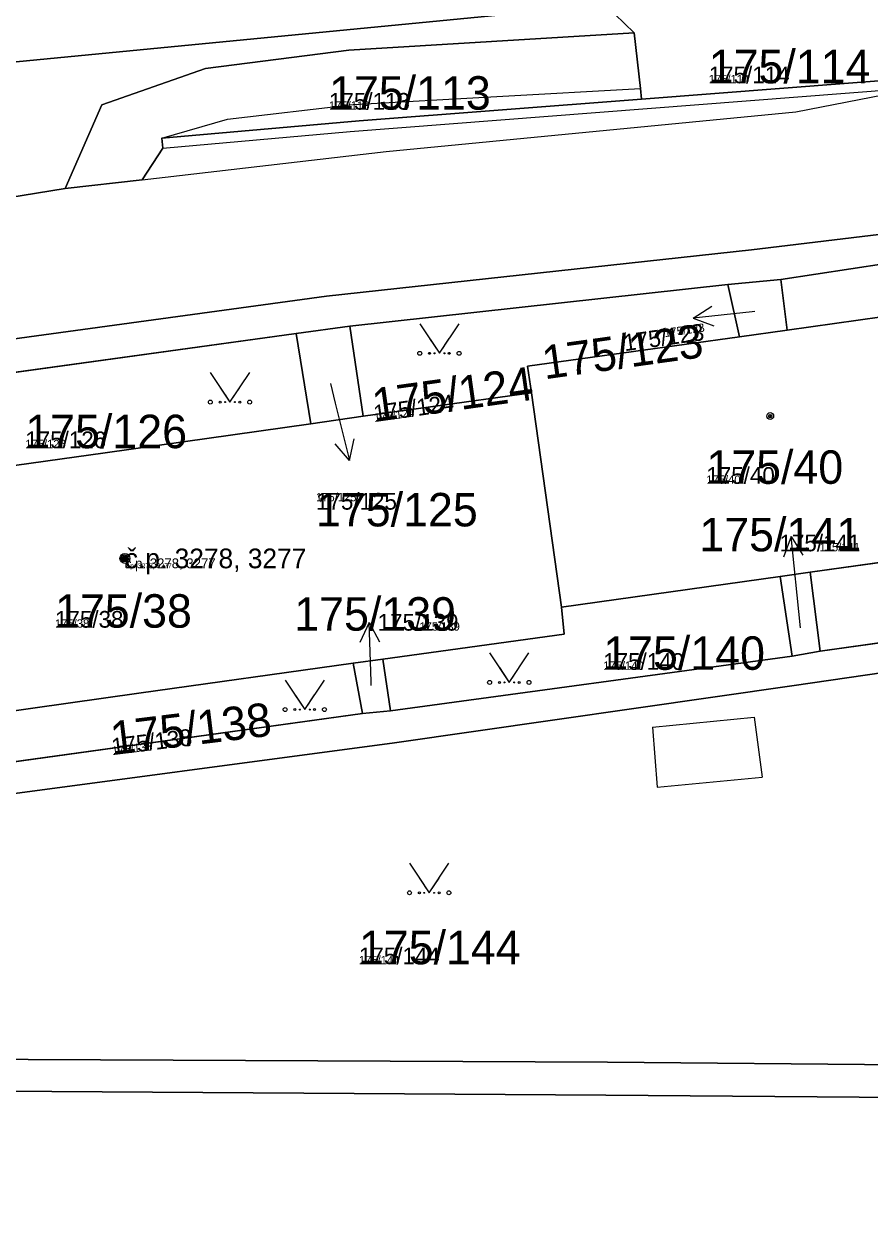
# Model space of a CAD drawing. Extents: x -759873 to -758487, y -975024 to -973516.
# Drawn here: x -759382.7 to -759339.7, y -974652.2 to -974591.1 of the extents above; entities that cross this region are included whole.
import ezdxf

# ---------------------------------------------------------------- set-up
doc = ezdxf.new("R2010")
doc.units = 0
for name, color, linetype in [('KAT_02_hranice parcel', 7, 'Continuous'), ('KAT_03_1000_st čísla parcelní', 7, 'Continuous'), ('KAT_03_1000_čísla parcelní', 7, 'Continuous'), ('KAT_03_1000_čísla popisná', 7, 'Continuous'), ('KAT_03_250_st čísla parcelní', 7, 'Continuous'), ('KAT_03_250_čísla parcelní', 7, 'Continuous'), ('KAT_03_250_čísla popisná', 7, 'Continuous'), ('KAT_03_500_st čísla parcelní', 7, 'Continuous'), ('KAT_03_500_čísla parcelní', 7, 'Continuous'), ('KAT_03_500_čísla popisná', 7, 'Continuous'), ('KAT_04_vnitřní kresba', 7, 'Continuous'), ('KAT_05_1000_značky kultur', 7, 'Continuous'), ('KAT_05_250_značky kultur', 7, 'Continuous'), ('KAT_05_500_značky kultur', 7, 'Continuous'), ('KAT_07_1000_značky budov', 7, 'Continuous'), ('KAT_07_250_značky budov', 7, 'Continuous'), ('KAT_07_500_značky budov', 7, 'Continuous'), ('KAT_12_pomocná šipka', 7, 'Continuous'), ('KAT_14_plocha_budovy', 7, 'Continuous'), ('KAT_14_plocha_pozemek', 7, 'Continuous')]:
    doc.layers.add(name, color=color, linetype=linetype)

msp = doc.modelspace()

# ---------------------------------------------------------------- linework, layer by layer
at = {"layer": 'KAT_02_hranice parcel'}
for p, q in [((-759351.66, -974591.58), (-759353.14, -974590.15)), ((-759366.12, -974606.48), (-759346.9, -974604.37)), ((-759346.9, -974604.37), (-759344.22, -974604.11)), ((-759346.9, -974604.37), (-759346.31, -974607.02)), ((-759344.22, -974604.11), (-759343.89, -974606.68)), ((-759335.47, -974605.5), (-759343.89, -974606.68)), ((-759387.52, -974609.43), (-759368.83, -974606.86)), ((-759368.83, -974606.86), (-759366.12, -974606.48)), ((-759368.83, -974606.86), (-759368.09, -974611.44)), ((-759366.12, -974606.48), (-759365.44, -974611.06)), ((-759343.89, -974606.68), (-759346.31, -974607.02)), ((-759356.89, -974609.86), (-759365.44, -974611.06)), ((-759355.36, -974620.75), (-759356.89, -974609.86)), ((-759365.44, -974611.06), (-759368.09, -974611.44)), ((-759342.73, -974618.98), (-759333.76, -974617.73)), ((-759344.25, -974619.2), (-759342.73, -974618.98)), ((-759342.21, -974622.99), (-759342.73, -974618.98)), ((-759355.36, -974620.75), (-759344.25, -974619.2)), ((-759343.64, -974623.25), (-759344.25, -974619.2)), ((-759342.21, -974622.99), (-759322.27, -974620.18)), ((-759364.05, -974626.02), (-759343.64, -974623.25)), ((-759343.64, -974623.25), (-759342.21, -974622.99)), ((-759365.95, -974623.61), (-759364.43, -974623.4)), ((-759365.46, -974626.16), (-759365.95, -974623.61)), ((-759364.05, -974626.02), (-759364.43, -974623.4)), ((-759385.53, -974628.94), (-759365.46, -974626.16)), ((-759365.46, -974626.16), (-759364.05, -974626.02))]:
    msp.add_line(p, q, dxfattribs=at)
for points in [[(-759283.48, -974554.45), (-759285.91, -974564.57), (-759295.56, -974575.71), (-759307.68, -974585.1), (-759325.38, -974591.13), (-759337.05, -974593.84), (-759351.29, -974594.94)], [(-759547.08, -974592.24), (-759448.7, -974599.4), (-759353.14, -974590.15)], [(-759380.57, -974599.49), (-759378.71, -974595.24), (-759373.45, -974593.39), (-759366.17, -974592.45), (-759351.66, -974591.58)], [(-759351.29, -974594.94), (-759351.35, -974594.4), (-759351.66, -974591.58)], [(-759351.29, -974594.94), (-759365.64, -974596.05), (-759375.66, -974596.93), (-759375.62, -974597.43), (-759376.67, -974599.04), (-759380.57, -974599.49)], [(-759458.72, -974606.33), (-759449.13, -974606.08), (-759449.06, -974608.45), (-759439.51, -974607.65), (-759419.34, -974604.87), (-759419.81, -974600.08), (-759405.17, -974598.13), (-759389.85, -974596.04), (-759389.12, -974600.88), (-759380.57, -974599.49)], [(-759458.92, -974616), (-759446.09, -974615.46), (-759436.69, -974614.55), (-759410.69, -974610.98), (-759388.86, -974607.91), (-759367.29, -974604.96), (-759345.7, -974602.61), (-759338.26, -974601.71), (-759332.17, -974600.63), (-759322.77, -974598.39)], [(-759344.22, -974604.11), (-759331.77, -974602.22), (-759325.4, -974600.84)], [(-759346.31, -974607.02), (-759357.08, -974608.52), (-759356.89, -974609.86)], [(-759368.09, -974611.44), (-759378.55, -974612.91), (-759386.93, -974614.09)], [(-759364.43, -974623.4), (-759355.22, -974622.12), (-759355.36, -974620.75)], [(-759312.58, -974644.18), (-759322.18, -974621.76), (-759327.25, -974622.45), (-759326.46, -974628.21), (-759332.53, -974629.17), (-759333.42, -974623.27), (-759343.54, -974624.73), (-759363.85, -974627.65), (-759385.69, -974630.57), (-759397.07, -974632.2), (-759408.02, -974633.91), (-759413.41, -974644.54)], [(-759385.82, -974626.4), (-759376.83, -974625.13), (-759365.95, -974623.61)], [(-759413.41, -974644.54), (-759400.59, -974643.97), (-759386.15, -974643.72), (-759353.03, -974643.87), (-759323.19, -974644.14), (-759312.58, -974644.18)], [(-759301.4, -974651.09), (-759309.93, -974650.8), (-759309.98, -974645.76), (-759323.06, -974645.78), (-759353.1, -974645.55), (-759386.38, -974645.33), (-759400.57, -974645.67), (-759414.93, -974646.26), (-759414.73, -974651.33), (-759436.14, -974652.5), (-759441.93, -974652.85), (-759450.38, -974653.47), (-759468.91, -974653.71), (-759482.38, -974653.4), (-759482.33, -974648.6), (-759512.45, -974647.4), (-759531.67, -974646.64), (-759556.45, -974645.57)]]:
    msp.add_lwpolyline(points, dxfattribs=at)
at = {"layer": 'KAT_03_1000_čísla popisná'}
msp.add_circle((-759377.54, -974618.28), 0.25, dxfattribs=at)
at = {"layer": 'KAT_03_250_čísla popisná'}
msp.add_circle((-759377.54, -974618.28), 0.0625, dxfattribs=at)
at = {"layer": 'KAT_03_500_čísla popisná'}
msp.add_circle((-759377.54, -974618.28), 0.125, dxfattribs=at)
at = {"layer": 'KAT_04_vnitřní kresba'}
for p, q in [((-759366.1, -974596.59), (-759337.01, -974594.34)), ((-759365.95, -974595.21), (-759351.35, -974594.4)), ((-759343.46, -974595.59), (-759337.01, -974594.34)), ((-759372.33, -974595.97), (-759365.95, -974595.21)), ((-759364.27, -974597.61), (-759343.46, -974595.59)), ((-759375.66, -974596.93), (-759372.33, -974595.97)), ((-759375.62, -974597.43), (-759366.1, -974596.59)), ((-759376.67, -974599.04), (-759364.27, -974597.61)), ((-759350.73, -974626.86), (-759345.57, -974626.34)), ((-759345.57, -974626.34), (-759345.16, -974629.39)), ((-759350.73, -974626.86), (-759350.49, -974629.9)), ((-759350.49, -974629.9), (-759345.16, -974629.39))]:
    msp.add_line(p, q, dxfattribs=at)
at = {"layer": 'KAT_05_1000_značky kultur'}
for points in [[(-759362.56, -974606.359), (-759361.56, -974607.86), (-759360.56, -974606.359)], [(-759373.2, -974608.839), (-759372.2, -974610.34), (-759371.2, -974608.839)], [(-759359.01, -974623.079), (-759358.01, -974624.58), (-759357.01, -974623.079)], [(-759369.4, -974624.459), (-759368.4, -974625.96), (-759367.4, -974624.459)], [(-759363.08, -974633.769), (-759362.08, -974635.27), (-759361.08, -974633.769)]]:
    msp.add_lwpolyline(points, dxfattribs=at)
for centre in [(-759362.56, -974607.859), (-759360.56, -974607.859), (-759373.2, -974610.339), (-759371.2, -974610.339), (-759359.01, -974624.579), (-759357.01, -974624.579), (-759369.4, -974625.959), (-759367.4, -974625.959), (-759363.08, -974635.269), (-759361.08, -974635.269)]:
    msp.add_circle(centre, 0.1, dxfattribs=at)
at = {"layer": 'KAT_05_250_značky kultur'}
for points in [[(-759361.81, -974607.485), (-759361.56, -974607.86), (-759361.31, -974607.485)], [(-759372.45, -974609.965), (-759372.2, -974610.34), (-759371.95, -974609.965)], [(-759358.26, -974624.205), (-759358.01, -974624.58), (-759357.76, -974624.205)], [(-759368.65, -974625.585), (-759368.4, -974625.96), (-759368.15, -974625.585)], [(-759362.33, -974634.895), (-759362.08, -974635.27), (-759361.83, -974634.895)]]:
    msp.add_lwpolyline(points, dxfattribs=at)
for centre in [(-759361.81, -974607.86), (-759361.31, -974607.86), (-759372.45, -974610.34), (-759371.95, -974610.34), (-759358.26, -974624.58), (-759357.76, -974624.58), (-759368.65, -974625.96), (-759368.15, -974625.96), (-759362.33, -974635.27), (-759361.83, -974635.27)]:
    msp.add_circle(centre, 0.025, dxfattribs=at)
at = {"layer": 'KAT_05_500_značky kultur'}
for points in [[(-759362.06, -974607.11), (-759361.56, -974607.86), (-759361.06, -974607.11)], [(-759372.7, -974609.59), (-759372.2, -974610.34), (-759371.7, -974609.59)], [(-759358.51, -974623.829), (-759358.01, -974624.58), (-759357.51, -974623.829)], [(-759368.9, -974625.209), (-759368.4, -974625.96), (-759367.9, -974625.209)], [(-759362.58, -974634.52), (-759362.08, -974635.27), (-759361.58, -974634.52)]]:
    msp.add_lwpolyline(points, dxfattribs=at)
for centre in [(-759362.06, -974607.86), (-759361.06, -974607.86), (-759372.7, -974610.34), (-759371.7, -974610.34), (-759358.51, -974624.58), (-759357.51, -974624.58), (-759368.9, -974625.96), (-759367.9, -974625.96), (-759362.58, -974635.27), (-759361.58, -974635.27)]:
    msp.add_circle(centre, 0.05, dxfattribs=at)
at = {"layer": 'KAT_07_1000_značky budov'}
for centre in [(-759344.757, -974611.049), (-759377.547, -974618.279)]:
    msp.add_circle(centre, 0.175, dxfattribs=at)
at = {"layer": 'KAT_07_250_značky budov'}
for centre in [(-759344.752, -974611.05), (-759377.542, -974618.28)]:
    msp.add_circle(centre, 0.0437, dxfattribs=at)
at = {"layer": 'KAT_07_500_značky budov'}
for centre in [(-759344.753, -974611.05), (-759377.543, -974618.28)]:
    msp.add_circle(centre, 0.0875, dxfattribs=at)
at = {"layer": 'KAT_12_pomocná šipka'}
for p, q in [((-759348.665, -974606.074), (-759347.721, -974605.471)), ((-759345.68, -974605.76), (-759348.665, -974606.074)), ((-759348.665, -974606.074), (-759347.616, -974606.467)), ((-759345.54, -974605.74), (-759345.68, -974605.76)), ((-759367.1, -974609.4), (-759366.86, -974610.39)), ((-759366.86, -974610.39), (-759366.134, -974613.302)), ((-759366.134, -974613.302), (-759365.89, -974612.209)), ((-759366.134, -974613.302), (-759366.862, -974612.451)), ((-759343.694, -974617.165), (-759344.087, -974618.214)), ((-759343.38, -974620.15), (-759343.694, -974617.165)), ((-759343.694, -974617.165), (-759343.091, -974618.109)), ((-759343.22, -974621.8), (-759343.38, -974620.15)), ((-759365.135, -974621.531), (-759365.6, -974622.549)), ((-759365.03, -974624.53), (-759365.135, -974621.531)), ((-759365.135, -974621.531), (-759364.599, -974622.514)), ((-759365.02, -974624.74), (-759365.03, -974624.53))]:
    msp.add_line(p, q, dxfattribs=at)
at = {"layer": 'KAT_14_plocha_budovy'}
for points in [[(-759356.89, -974609.86), (-759355.36, -974620.75), (-759344.25, -974619.2), (-759342.73, -974618.98), (-759333.76, -974617.73), (-759322.92, -974616.21), (-759321.35, -974615.99), (-759312.14, -974614.7), (-759313.85, -974602.47), (-759322.54, -974603.69), (-759325.1, -974604.05), (-759335.47, -974605.5), (-759343.89, -974606.68), (-759346.31, -974607.02), (-759357.08, -974608.52)], [(-759400.2, -974615.95), (-759398.65, -974626.98), (-759398.42, -974628.19), (-759387.39, -974626.63), (-759385.82, -974626.4), (-759376.83, -974625.13), (-759365.95, -974623.61), (-759364.43, -974623.4), (-759355.22, -974622.12), (-759355.36, -974620.75), (-759356.89, -974609.86), (-759365.44, -974611.06), (-759368.09, -974611.44), (-759378.55, -974612.91), (-759386.93, -974614.09), (-759389.49, -974614.45)]]:
    msp.add_lwpolyline(points, close=True, dxfattribs=at)
at = {"layer": 'KAT_14_plocha_pozemek'}
for points in [[(-759283.48, -974554.45), (-759289.47, -974556.76), (-759288.81, -974562.93), (-759306.77, -974580.66), (-759307.51, -974581.39), (-759331.97, -974589.97), (-759351.99, -974590.04), (-759353.14, -974590.15), (-759351.66, -974591.58), (-759351.35, -974594.4), (-759351.29, -974594.94), (-759337.05, -974593.84), (-759325.38, -974591.13), (-759307.68, -974585.1), (-759295.56, -974575.71), (-759285.91, -974564.57)], [(-759353.14, -974590.15), (-759355.46, -974587.9), (-759370.19, -974589.29), (-759382.8, -974590.19), (-759390.95, -974590), (-759405.56, -974590.95), (-759424.58, -974592.4), (-759444.22, -974592.7), (-759459.82, -974591.36), (-759476.84, -974591.63), (-759487.86, -974590.72), (-759504.11, -974587.5), (-759520.18, -974585.89), (-759541.79, -974583.51), (-759547.64, -974583.57), (-759547.08, -974592.24), (-759448.7, -974599.4)], [(-759351.29, -974594.94), (-759351.35, -974594.4), (-759351.66, -974591.58), (-759366.17, -974592.45), (-759373.45, -974593.39), (-759378.71, -974595.24), (-759380.57, -974599.49), (-759376.67, -974599.04), (-759375.62, -974597.43), (-759375.66, -974596.93), (-759365.64, -974596.05)], [(-759343.89, -974606.68), (-759335.47, -974605.5), (-759325.1, -974604.05), (-759325.4, -974600.84), (-759331.77, -974602.22), (-759344.22, -974604.11)], [(-759365.44, -974611.06), (-759356.89, -974609.86), (-759357.08, -974608.52), (-759346.31, -974607.02), (-759346.9, -974604.37), (-759366.12, -974606.48)], [(-759346.31, -974607.02), (-759343.89, -974606.68), (-759344.22, -974604.11), (-759346.9, -974604.37)], [(-759343.89, -974606.68), (-759346.31, -974607.02), (-759357.08, -974608.52), (-759356.89, -974609.86), (-759355.36, -974620.75), (-759344.25, -974619.2), (-759342.73, -974618.98), (-759333.76, -974617.73), (-759335.47, -974605.5)], [(-759386.93, -974614.09), (-759378.55, -974612.91), (-759368.09, -974611.44), (-759368.83, -974606.86), (-759387.52, -974609.43)], [(-759368.09, -974611.44), (-759365.44, -974611.06), (-759366.12, -974606.48), (-759368.83, -974606.86)], [(-759387.39, -974626.63), (-759385.82, -974626.4), (-759376.83, -974625.13), (-759365.95, -974623.61), (-759364.43, -974623.4), (-759355.22, -974622.12), (-759355.36, -974620.75), (-759356.89, -974609.86), (-759365.44, -974611.06), (-759368.09, -974611.44), (-759378.55, -974612.91), (-759386.93, -974614.09), (-759389.49, -974614.45), (-759400.2, -974615.95), (-759398.65, -974626.98), (-759398.42, -974628.19)], [(-759322.27, -974620.18), (-759322.92, -974616.21), (-759333.76, -974617.73), (-759342.73, -974618.98), (-759342.21, -974622.99)], [(-759342.21, -974622.99), (-759342.73, -974618.98), (-759344.25, -974619.2), (-759343.64, -974623.25)], [(-759343.64, -974623.25), (-759344.25, -974619.2), (-759355.36, -974620.75), (-759355.22, -974622.12), (-759364.43, -974623.4), (-759364.05, -974626.02)], [(-759322.18, -974621.76), (-759327.25, -974622.45), (-759326.46, -974628.21), (-759332.53, -974629.17), (-759333.42, -974623.27), (-759343.54, -974624.73), (-759363.85, -974627.65), (-759385.69, -974630.57), (-759397.07, -974632.2), (-759408.02, -974633.91), (-759413.41, -974644.54), (-759400.59, -974643.97), (-759386.15, -974643.72), (-759353.03, -974643.87), (-759323.19, -974644.14), (-759312.58, -974644.18)], [(-759365.46, -974626.16), (-759365.95, -974623.61), (-759376.83, -974625.13), (-759385.82, -974626.4), (-759385.53, -974628.94)], [(-759364.05, -974626.02), (-759364.43, -974623.4), (-759365.95, -974623.61), (-759365.46, -974626.16)]]:
    msp.add_lwpolyline(points, close=True, dxfattribs=at)
for points in [[(-759388.86, -974607.91), (-759367.29, -974604.96), (-759345.7, -974602.61), (-759338.26, -974601.71), (-759332.17, -974600.63), (-759322.77, -974598.39), (-759321.53, -974598.09), (-759304.96, -974592.94), (-759296.09, -974586.64)], [(-759458.72, -974606.33), (-759449.13, -974606.08), (-759449.06, -974608.45), (-759439.51, -974607.65), (-759419.34, -974604.87), (-759419.81, -974600.08), (-759405.17, -974598.13), (-759389.85, -974596.04), (-759389.12, -974600.88), (-759380.57, -974599.49), (-759378.71, -974595.24), (-759373.45, -974593.39), (-759366.17, -974592.45), (-759351.66, -974591.58), (-759353.14, -974590.15), (-759448.7, -974599.4), (-759547.08, -974592.24)], [(-759387.52, -974609.43), (-759368.83, -974606.86), (-759366.12, -974606.48), (-759346.9, -974604.37), (-759344.22, -974604.11), (-759331.77, -974602.22), (-759325.4, -974600.84), (-759323.26, -974600.42), (-759309.48, -974598.24), (-759307.88, -974598.12), (-759290.09, -974596.67), (-759278.62, -974595.1), (-759273.24, -974594.5), (-759273.36, -974593.06), (-759278.86, -974593.63), (-759290.19, -974595.17), (-759308.05, -974596.67), (-759322.62, -974598.98), (-759322.77, -974598.39), (-759332.17, -974600.63), (-759338.26, -974601.71), (-759345.7, -974602.61), (-759367.29, -974604.96), (-759388.86, -974607.91)], [(-759337.05, -974593.84), (-759351.29, -974594.94), (-759365.64, -974596.05), (-759375.66, -974596.93), (-759375.62, -974597.43)], [(-759375.62, -974597.43), (-759376.67, -974599.04), (-759380.57, -974599.49), (-759389.12, -974600.88), (-759389.85, -974596.04), (-759405.17, -974598.13), (-759419.81, -974600.08), (-759419.34, -974604.87), (-759439.51, -974607.65), (-759449.06, -974608.45), (-759449.13, -974606.08), (-759458.72, -974606.33)], [(-759326.46, -974628.21), (-759327.25, -974622.45), (-759322.18, -974621.76), (-759312.58, -974644.18), (-759309.99, -974643.67), (-759311.21, -974642.79), (-759320.29, -974621.47), (-759300.68, -974618.84), (-759300.61, -974617.23), (-759305.11, -974617.79), (-759307.88, -974598.12), (-759309.48, -974598.24), (-759306.76, -974618.14), (-759320.81, -974620), (-759322.27, -974620.18), (-759342.21, -974622.99), (-759343.64, -974623.25), (-759364.05, -974626.02), (-759365.46, -974626.16), (-759385.53, -974628.94)], [(-759457.23, -974651.73), (-759455.76, -974651.64), (-759455.81, -974650.42), (-759455.66, -974648.47), (-759452.74, -974644.77), (-759451.74, -974643.76), (-759449.7, -974643.81), (-759449.73, -974641.73), (-759452.21, -974641.62), (-759452.03, -974640.02), (-759447.2, -974639.07), (-759424.37, -974636.08), (-759410.2, -974634.07), (-759415.08, -974644.61), (-759413.41, -974644.54), (-759408.02, -974633.91), (-759397.07, -974632.2), (-759385.69, -974630.57), (-759363.85, -974627.65), (-759343.54, -974624.73), (-759333.42, -974623.27), (-759332.53, -974629.17), (-759326.46, -974628.21)], [(-759386.38, -974645.33), (-759353.1, -974645.55), (-759323.06, -974645.78), (-759309.98, -974645.76), (-759309.93, -974650.8), (-759301.4, -974651.09), (-759301.35, -974650.09), (-759309.09, -974649.92), (-759308.98, -974643.69), (-759309.99, -974643.67), (-759312.58, -974644.18), (-759323.19, -974644.14), (-759353.03, -974643.87), (-759386.15, -974643.72)], [(-759297.43, -974657.37), (-759290.03, -974651.55), (-759299.44, -974651.21), (-759301.4, -974651.09), (-759309.93, -974650.8), (-759309.98, -974645.76), (-759323.06, -974645.78), (-759353.1, -974645.55), (-759386.38, -974645.33), (-759400.57, -974645.67), (-759414.93, -974646.26), (-759414.73, -974651.33), (-759436.14, -974652.5)]]:
    msp.add_lwpolyline(points, dxfattribs=at)

# ---------------------------------------------------------------- texts
at = {"layer": 'KAT_03_1000_st čísla parcelní'}
for s, p in [('175/40', (-759348, -974614.49)), ('175/38', (-759381.09, -974621.799))]:
    msp.add_text(s, height=1.7, dxfattribs=at).set_placement(p)
at = {"layer": 'KAT_03_1000_čísla parcelní'}
for s, p in [('175/114', (-759347.88, -974594.14)), ('175/113', (-759367.17, -974595.48)), ('175/126', (-759382.6, -974612.679)), ('175/125', (-759367.83, -974616.653)), ('175/141', (-759348.356, -974617.919)), ('175/139', (-759368.936, -974621.95)), ('175/140', (-759353.24, -974623.94)), ('175/144', (-759365.65, -974638.9))]:
    msp.add_text(s, height=1.7, dxfattribs=at).set_placement(p)
for s, rotation, p in [('175/123', 8, (-759356.217, -974609.184)), ('175/124', 8, (-759364.851, -974611.351)), ('175/138', 7, (-759378.166, -974628.273))]:
    msp.add_text(s, height=1.7, rotation=rotation, dxfattribs=at).set_placement(p)
at = {"layer": 'KAT_03_1000_čísla popisná'}
msp.add_text('č.p. 3278, 3277', height=1, dxfattribs=at).set_placement((-759377.54, -974618.78))
at = {"layer": 'KAT_03_250_st čísla parcelní'}
for s, p in [('175/40', (-759348, -974614.49)), ('175/38', (-759381.09, -974621.799))]:
    msp.add_text(s, height=0.425, dxfattribs=at).set_placement(p)
at = {"layer": 'KAT_03_250_čísla parcelní'}
for s, p in [('175/114', (-759347.88, -974594.14)), ('175/113', (-759367.17, -974595.48)), ('175/126', (-759382.6, -974612.679)), ('175/125', (-759367.83, -974615.378)), ('175/141', (-759342.247, -974617.919)), ('175/139', (-759362.578, -974621.95)), ('175/140', (-759353.24, -974623.94)), ('175/144', (-759365.65, -974638.9))]:
    msp.add_text(s, height=0.425, dxfattribs=at).set_placement(p)
for s, rotation, p in [('175/123', 8, (-759350.101, -974607.037)), ('175/124', 8, (-759364.851, -974611.351)), ('175/138', 7, (-759378.166, -974628.273))]:
    msp.add_text(s, height=0.425, rotation=rotation, dxfattribs=at).set_placement(p)
at = {"layer": 'KAT_03_250_čísla popisná'}
msp.add_text('č.p. 3278, 3277', height=0.25, dxfattribs=at).set_placement((-759377.54, -974618.78))
at = {"layer": 'KAT_03_500_st čísla parcelní'}
for s, p in [('175/40', (-759348, -974614.49)), ('175/38', (-759381.09, -974621.799))]:
    msp.add_text(s, height=0.85, dxfattribs=at).set_placement(p)
at = {"layer": 'KAT_03_500_čísla parcelní'}
for s, p in [('175/114', (-759347.88, -974594.14)), ('175/113', (-759367.17, -974595.48)), ('175/126', (-759382.6, -974612.679)), ('175/125', (-759367.83, -974615.803)), ('175/141', (-759344.284, -974617.919)), ('175/139', (-759364.698, -974621.95)), ('175/140', (-759353.24, -974623.94)), ('175/144', (-759365.65, -974638.9))]:
    msp.add_text(s, height=0.85, dxfattribs=at).set_placement(p)
for s, rotation, p in [('175/123', 8, (-759352.139, -974607.753)), ('175/124', 8, (-759364.851, -974611.351)), ('175/138', 7, (-759378.166, -974628.273))]:
    msp.add_text(s, height=0.85, rotation=rotation, dxfattribs=at).set_placement(p)
at = {"layer": 'KAT_03_500_čísla popisná'}
msp.add_text('č.p. 3278, 3277', height=0.5, dxfattribs=at).set_placement((-759377.54, -974618.78))

doc.saveas('drawing.dxf')
